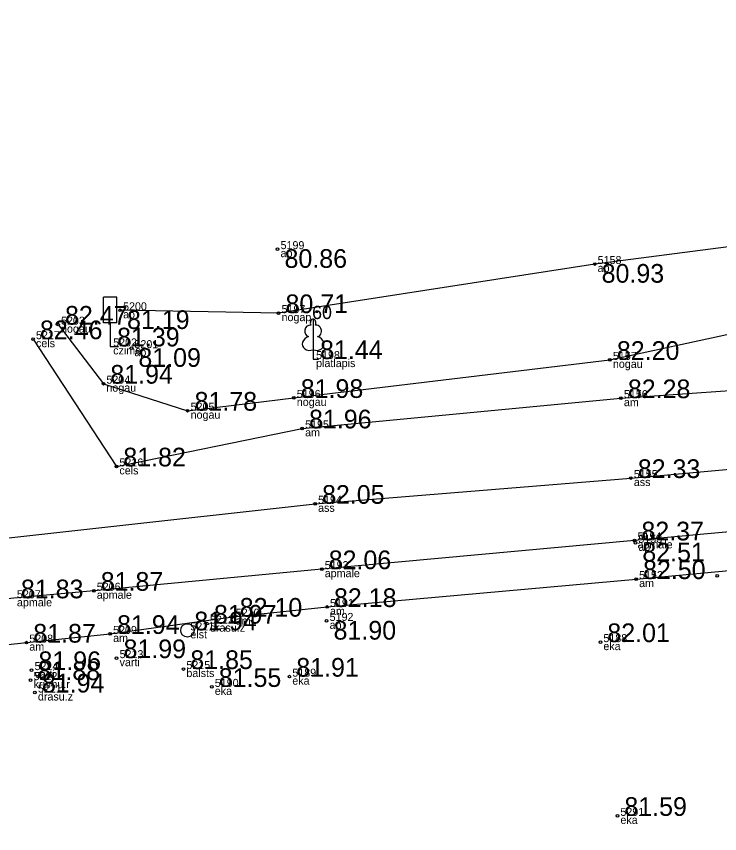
# Model space of a CAD drawing. Extents: x 614911 to 615803, y 262110 to 264311.
# Drawn here: x 615575.7 to 615602.05, y 263102.4 to 263133.02 of the extents above; entities that cross this region are included whole.
import ezdxf

# ---------------------------------------------------------------- set-up
doc = ezdxf.new("R2010")
doc.units = 0
for name, color, linetype in [('Level 1', 7, 'Continuous'), ('Level 16', 7, 'Continuous'), ('Level 18', 7, 'Continuous'), ('Level 31', 7, 'Continuous'), ('Level 37', 7, 'Continuous'), ('Level 53', 7, 'Continuous'), ('Level 54', 7, 'Continuous'), ('Level 57', 7, 'Continuous'), ('Level 58', 7, 'Continuous')]:
    doc.layers.add(name, color=color, linetype=linetype)

msp = doc.modelspace()

# ---------------------------------------------------------------- linework, layer by layer
at = {"layer": 'Level 1'}
for p, q in [((615586.82, 263120.529), (615586.82, 263120.182)), ((615586.82, 263120.182), (615587.02, 263120.182))]:
    msp.add_line(p, q, dxfattribs=at)
for points in [[(615586.82, 263121.682), (615586.82, 263120.529)], [(615586.91, 263121.45), (615586.909, 263121.451)]]:
    msp.add_lwpolyline(points, dxfattribs=at)
for centre, major_axis, ratio, start_param, end_param in [((615586.82, 263121.532), (0, -0.15), 0.707107, 3.14537, 5.287485), ((615586.82, 263121.532), (0, -0.15), 0.707107, 0.995701, 3.137816), ((615586.692, 263121.237), (-0.039, -0.212), 0.861323, 3.141593, 6.283185), ((615586.948, 263121.237), (0.039, -0.212), 0.861323, 0, 3.141593), ((615586.73, 263120.775), (0.307, 0.095), 0.814445, 1.570796, 4.752015), ((615586.91, 263120.775), (-0.307, 0.095), 0.814445, 1.531171, 4.712389)]:
    msp.add_ellipse(centre, major_axis=major_axis, ratio=ratio, start_param=start_param, end_param=end_param, dxfattribs=at)
at = {"layer": 'Level 16'}
for p, q in [((615579.464, 263122.504), (615578.964, 263122.504)), ((615578.964, 263121.535), (615578.964, 263122.504)), ((615579.464, 263121.535), (615579.464, 263122.504)), ((615579.464, 263121.535), (615578.964, 263121.535)), ((615579.218, 263121.535), (615579.218, 263120.657)), ((615579.218, 263120.657), (615579.533, 263120.657))]:
    msp.add_line(p, q, dxfattribs=at)
at = {"layer": 'Level 18'}
msp.add_circle((615582.109, 263110.018), 0.25, dxfattribs=at)
at = {"layer": 'Level 31'}
for points in [[(615577.265, 263121.472), (615578.964, 263119.261), (615582.119, 263118.249), (615586.097, 263118.727), (615597.94, 263120.152), (615604.458, 263121.561), (615607.554, 263124.237), (615607.727, 263127.876), (615607.383, 263130.733)], [(615604.258, 263125.988), (615602.376, 263124.385), (615597.369, 263123.744), (615585.526, 263121.903), (615579.589, 263122.009)]]:
    msp.add_lwpolyline(points, dxfattribs=at)
at = {"layer": 'Level 37'}
for points in [[(615598.724, 263115.726), (615634.884, 263119.01), (615648.105, 263119.92), (615667.349, 263121.963), (615687.532, 263124.19), (615702.985, 263125.929), (615769.011, 263133.023)], [(615576.326, 263120.927), (615579.45, 263116.161), (615586.408, 263117.585), (615598.352, 263118.718), (615605.463, 263119.214)], [(615506.221, 263104.881), (615543.006, 263109.898), (615562.345, 263112.039), (615586.894, 263114.763), (615598.724, 263115.726)], [(615615.564, 263114.904), (615598.86, 263113.389), (615587.144, 263112.311), (615578.603, 263111.502), (615575.613, 263111.22), (615562.602, 263109.796), (615557.204, 263109.209), (615543.206, 263107.641), (615534.176, 263106.615), (615506.6, 263102.579)], [(615517.756, 263102.402), (615538.559, 263105.495), (615539.553, 263105.604), (615543.433, 263106), (615557.279, 263107.505), (615557.417, 263106.667), (615562.611, 263107.075), (615562.621, 263108.088), (615576.076, 263109.559), (615579.215, 263109.885), (615583.81, 263110.531), (615587.341, 263110.894), (615598.921, 263111.94), (615605.888, 263112.584)]]:
    msp.add_lwpolyline(points, dxfattribs=at)
at = {"layer": 'Level 57'}
for centre in [(615585.489, 263124.301), (615597.369, 263123.744), (615579.589, 263122.009), (615585.526, 263121.903), (615577.265, 263121.472), (615576.326, 263120.927), (615580.014, 263120.591), (615597.94, 263120.152), (615578.964, 263119.261), (615586.097, 263118.727), (615598.352, 263118.718), (615582.119, 263118.249), (615586.408, 263117.585), (615579.45, 263116.161), (615598.724, 263115.726), (615586.894, 263114.76), (615598.86, 263113.389), (615598.894, 263113.299), (615587.144, 263112.311), (615598.921, 263111.94), (615601.962, 263112.058), (615578.603, 263111.502), (615587.341, 263110.894), (615583.81, 263110.531), (615587.327, 263110.372), (615582.845, 263110.27), (615579.215, 263109.885), (615576.076, 263109.559), (615597.583, 263109.578), (615579.458, 263108.977), (615576.272, 263108.53), (615581.961, 263108.569), (615576.237, 263108.153), (615585.93, 263108.284), (615583.025, 263107.9), (615576.399, 263107.69), (615598.221, 263103.068)]:
    msp.add_circle(centre, 0.05, dxfattribs=at)
at = {"layer": 'Level 58'}
for centre in [(615585.489, 263124.301), (615597.369, 263123.744), (615579.589, 263122.009), (615585.526, 263121.903), (615577.265, 263121.472), (615576.326, 263120.927), (615580.014, 263120.591), (615597.94, 263120.152), (615578.964, 263119.261), (615586.097, 263118.727), (615598.352, 263118.718), (615582.119, 263118.249), (615586.408, 263117.585), (615579.45, 263116.161), (615598.724, 263115.726), (615586.894, 263114.76), (615598.86, 263113.389), (615598.894, 263113.299), (615587.144, 263112.311), (615598.921, 263111.94), (615601.962, 263112.058), (615578.603, 263111.502), (615587.341, 263110.894), (615583.81, 263110.531), (615587.327, 263110.372), (615582.845, 263110.27), (615579.215, 263109.885), (615576.076, 263109.559), (615597.583, 263109.578), (615579.458, 263108.977), (615576.272, 263108.53), (615581.961, 263108.569), (615576.237, 263108.153), (615585.93, 263108.284), (615583.025, 263107.9), (615576.399, 263107.69), (615598.221, 263103.068)]:
    msp.add_circle(centre, 0.05, dxfattribs=at)

# ---------------------------------------------------------------- texts
at = {"layer": 'Level 1'}
msp.add_text(' 60', height=0.5, dxfattribs=at).set_placement((615586.595, 263121.682))
at = {"layer": 'Level 53'}
for s, p in [(' ap', (615585.489, 263124.001)), (' ap', (615597.369, 263123.444)), (' ap', (615579.589, 263121.709)), (' nogap', (615585.526, 263121.603)), (' nogau', (615577.265, 263121.172)), (' cels', (615576.326, 263120.627)), (' czime', (615579.218, 263120.357)), (' ap', (615580.014, 263120.291)), (' platlapis', (615586.82, 263119.882)), (' nogau', (615597.94, 263119.852)), (' nogau', (615578.964, 263118.961)), (' nogau', (615586.097, 263118.427)), (' am', (615598.352, 263118.418)), (' nogau', (615582.119, 263117.949)), (' am', (615586.408, 263117.285)), (' cels', (615579.45, 263115.861)), (' ass', (615598.724, 263115.426)), (' ass', (615586.894, 263114.46)), (' apmale', (615598.86, 263113.089)), (' ap', (615598.894, 263112.999)), (' apmale', (615587.144, 263112.011)), (' am', (615598.921, 263111.64)), (' apmale', (615578.603, 263111.202)), (' apmale', (615575.613, 263110.92)), (' am', (615587.341, 263110.594)), (' am', (615583.81, 263110.231)), (' elst', (615582.109, 263109.718)), (' drasu.z', (615582.845, 263109.97)), (' ap', (615587.327, 263110.072)), (' am', (615579.215, 263109.585)), (' am', (615576.076, 263109.259)), (' eka', (615597.583, 263109.278)), (' varti', (615579.458, 263108.677)), (' varti', (615576.272, 263108.23)), (' balsts', (615581.961, 263108.269)), (' eka', (615585.93, 263107.984)), (' krumu.r', (615576.237, 263107.853)), (' eka', (615583.025, 263107.6)), (' drasu.z', (615576.399, 263107.39)), (' eka', (615598.221, 263102.768))]:
    msp.add_text(s, height=0.3, dxfattribs=at).set_placement(p)
at = {"layer": 'Level 54'}
for s, p in [(' 5199', (615585.489, 263124.301)), (' 5158', (615597.369, 263123.744)), (' 5200', (615579.589, 263122.009)), (' 5197', (615585.526, 263121.903)), (' 5203', (615577.265, 263121.472)), (' 5217', (615576.326, 263120.927)), (' 5202', (615579.218, 263120.657)), (' 5201', (615580.014, 263120.591)), (' 5198', (615586.82, 263120.182)), (' 5157', (615597.94, 263120.152)), (' 5204', (615578.964, 263119.261)), (' 5196', (615586.097, 263118.727)), (' 5156', (615598.352, 263118.718)), (' 5205', (615582.119, 263118.249)), (' 5195', (615586.408, 263117.585)), (' 5216', (615579.45, 263116.161)), (' 5155', (615598.724, 263115.726)), (' 5194', (615586.894, 263114.76)), (' 5154', (615598.86, 263113.389)), (' 5153', (615598.894, 263113.299)), (' 5193', (615587.144, 263112.311)), (' 5152', (615598.921, 263111.94)), (' 5206', (615578.603, 263111.502)), (' 5207', (615575.613, 263111.22)), (' 5191', (615587.341, 263110.894)), (' 5210', (615583.81, 263110.531)), (' 5192', (615587.327, 263110.372)), (' 5212', (615582.845, 263110.27)), (' 5209', (615579.215, 263109.885)), (' 5211', (615582.109, 263110.018)), (' 5208', (615576.076, 263109.559)), (' 5188', (615597.583, 263109.578)), (' 5213', (615579.458, 263108.977)), (' 5214', (615576.272, 263108.53)), (' 5215', (615581.961, 263108.569)), (' 5189', (615585.93, 263108.284)), (' 5222', (615576.237, 263108.153)), (' 5190', (615583.025, 263107.9)), (' 5221', (615576.399, 263107.69)), (' 5291', (615598.221, 263103.068))]:
    msp.add_text(s, height=0.3, dxfattribs=at).set_placement(p)
at = {"layer": 'Level 58'}
for s, p in [(' 80.86', (615585.489, 263123.601)), (' 80.93', (615597.369, 263123.044)), (' 80.71', (615585.526, 263121.903)), (' 82.47', (615577.265, 263121.472)), (' 81.19', (615579.589, 263121.309)), (' 82.46', (615576.326, 263120.927)), (' 81.39', (615579.218, 263120.657)), (' 81.44', (615586.82, 263120.182)), (' 82.20', (615597.94, 263120.152)), (' 81.09', (615580.014, 263119.891)), (' 81.94', (615578.964, 263119.261)), (' 81.98', (615586.097, 263118.727)), (' 82.28', (615598.352, 263118.718)), (' 81.78', (615582.119, 263118.249)), (' 81.96', (615586.408, 263117.585)), (' 81.82', (615579.45, 263116.161)), (' 82.33', (615598.724, 263115.726)), (' 82.05', (615586.894, 263114.76)), (' 82.37', (615598.86, 263113.389)), (' 82.51', (615598.894, 263112.599)), (' 82.06', (615587.144, 263112.311)), (' 82.50', (615598.921, 263111.94)), (' 81.87', (615578.603, 263111.502)), (' 81.83', (615575.613, 263111.22)), (' 82.18', (615587.341, 263110.894)), (' 81.97', (615582.845, 263110.27)), (' 82.10', (615583.81, 263110.531)), (' 81.94', (615582.109, 263110.018)), (' 81.94', (615579.215, 263109.885)), (' 81.90', (615587.327, 263109.672)), (' 81.87', (615576.076, 263109.559)), (' 82.01', (615597.583, 263109.578)), (' 81.99', (615579.458, 263108.977)), (' 81.96', (615576.272, 263108.53)), (' 81.85', (615581.961, 263108.569)), (' 81.88', (615576.237, 263108.153)), (' 81.91', (615585.93, 263108.284)), (' 81.55', (615583.025, 263107.9)), (' 81.94', (615576.399, 263107.69)), (' 81.59', (615598.221, 263103.068))]:
    msp.add_text(s, height=0.7, dxfattribs=at).set_placement(p)

doc.saveas('drawing.dxf')
